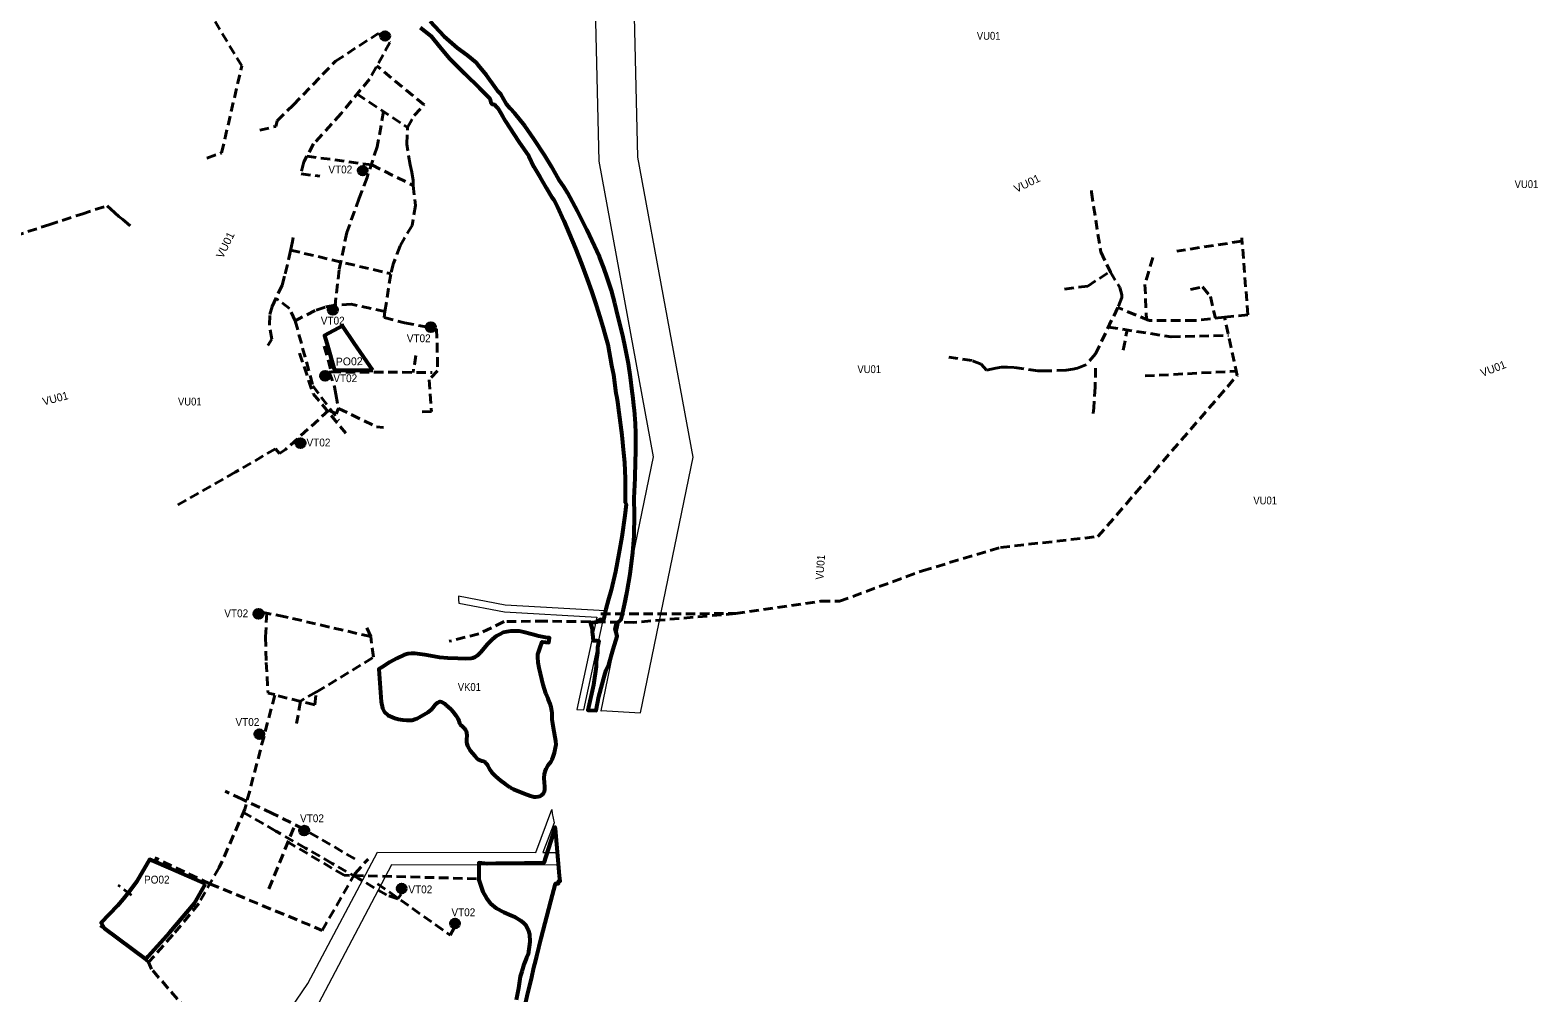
# Model space of a CAD drawing. Extents: x -650145 to -642675, y -1074338 to -1066724.
# Drawn here: x -646512 to -642675, y -1071699 to -1069249 of the extents above; entities that cross this region are included whole.
import ezdxf

# ---------------------------------------------------------------- set-up
doc = ezdxf.new("R2010")
doc.units = 0
doc.header["$LTSCALE"] = 8
doc.linetypes.add('MEDIUM_DASHED', pattern=[4.5, 3, -1.5])
for name, color, linetype in [('1', 7, 'Continuous'), ('17', 7, 'Continuous'), ('2', 7, 'Continuous'), ('5', 7, 'Continuous')]:
    doc.layers.add(name, color=color, linetype=linetype)
for name, color, linetype, lineweight in [('12', 7, 'MEDIUM_DASHED', 40), ('15', 7, 'Continuous', 13), ('45', 7, 'Continuous', 53), ('46', 7, 'Continuous', 53)]:
    doc.layers.add(name, color=color, linetype=linetype, lineweight=lineweight)

msp = doc.modelspace()

# ---------------------------------------------------------------- hatches: boundary and pattern name
at = {"layer": '15'}
for points in [[(-645597.068, -1069264.181, 1), (-645620.593, -1069264.181, 1)], [(-645654.023, -1069606.85, 1), (-645677.548, -1069606.85, 1)], [(-645729.982, -1069961.372, 1), (-645753.507, -1069961.372, 1)], [(-645480.488, -1070005.174, 1), (-645504.013, -1070005.174, 1)], [(-645749.33, -1070128.96, 1), (-645772.855, -1070128.96, 1)], [(-645812.096, -1070300.527, 1), (-645835.621, -1070300.527, 1)], [(-645919.09, -1070734.667, 1), (-645942.615, -1070734.667, 1)], [(-645917.104, -1071041.111, 1), (-645940.629, -1071041.111, 1)], [(-645802.757, -1071286.29, 1), (-645826.282, -1071286.29, 1)], [(-645554.856, -1071433.585, 1), (-645578.381, -1071433.585, 1)], [(-645418.959, -1071522.908, 1), (-645442.484, -1071522.908, 1)]]:
    msp.add_hatch(color=256, dxfattribs=at).paths.add_polyline_path(points)

# ---------------------------------------------------------------- linework, layer by layer
at = {"layer": '12'}
for p, q in [((-645679.959, -1069412.046), (-645551.493, -1069496.874)), ((-645849.328, -1069809.196), (-645594.304, -1069869.281)), ((-643429.636, -1069786.459), (-643594.181, -1069811.599)), ((-643730.467, -1070063.614), (-643720.12, -1070012.253)), ((-645530.465, -1070076.92), (-645537.502, -1070120.198)), ((-643674.528, -1070129.34), (-643442.257, -1070116.937)), ((-645787.95, -1070966.128), (-645887.342, -1070941.864)), ((-645904.71, -1071434.718), (-645838.309, -1071272.923)), ((-645713.277, -1071399.789), (-645855.82, -1071315.589)), ((-646054.42, -1071421.627), (-646194.458, -1071355.655)), ((-646254.398, -1071450.366), (-646287.777, -1071424.84)), ((-645375.745, -1071408.757), (-645713.277, -1071399.789))]:
    msp.add_line(p, q, dxfattribs=at)
for points in [[(-646062.183, -1069574.695), (-646024.736, -1069561.612), (-645973.562, -1069340.254), (-646092.013, -1069143.037), (-646157.557, -1069015.41), (-646220.085, -1068916.892), (-646248.016, -1068862.258), (-646295.932, -1068894.5), (-646451.322, -1069032.874)], [(-645927.806, -1069503.664), (-645886.806, -1069494.297), (-645883.788, -1069480.205), (-645842.55, -1069439.942), (-645734.927, -1069328.215), (-645626.154, -1069257.704), (-645596.435, -1069280.712), (-645648.533, -1069373.739), (-645720.378, -1069461.316), (-645790.62, -1069538.59), (-645815.779, -1069584.682), (-645822.696, -1069614.711), (-645775.097, -1069621.255)], [(-645807.67, -1069569.827), (-645642.853, -1069592.369), (-645537.006, -1069644.608), (-645537.068, -1069631.54), (-645540.509, -1069610.611), (-645545.036, -1069592.007), (-645553.718, -1069539.481), (-645551.493, -1069496.874), (-645535.107, -1069466.529), (-645509.579, -1069439.682), (-645629.872, -1069340.417)], [(-645612.686, -1069456.467), (-645628.75, -1069545.873), (-645654.668, -1069623.875), (-645674.387, -1069676.46), (-645706.032, -1069763.934), (-645725.616, -1069858.975), (-645736.083, -1069949.319)], [(-645537.006, -1069644.608), (-645531.552, -1069695.67), (-645540.071, -1069746.311), (-645570.504, -1069798.227), (-645587.257, -1069841.96), (-645594.542, -1069870.205), (-645609.199, -1069964.997), (-645695.3, -1069946.789), (-645735.674, -1069949.294), (-645761.611, -1069954.176), (-645786.679, -1069962.538), (-645837.185, -1069988.794), (-645851.6, -1069958.035), (-645886.355, -1069931.852)], [(-643810.627, -1069657.665), (-643811.385, -1069662.021), (-643787.529, -1069813.369), (-643763.019, -1069865.538), (-643739.057, -1069904.105), (-643733.398, -1069922.453), (-643733.672, -1069929.3), (-643744.205, -1069955.268), (-643800.43, -1070073.069), (-643825.501, -1070101.354), (-643846.88, -1070109.266), (-643858.108, -1070112.46), (-643875.543, -1070114.925), (-643927.411, -1070116.568), (-643947.688, -1070115.858), (-644007.981, -1070107.962), (-644024.686, -1070106.729), (-644040.027, -1070107.201), (-644054.663, -1070109.432), (-644077.983, -1070114.354), (-644091.49, -1070099.721), (-644115.344, -1070090.018), (-644174.372, -1070081.528)], [(-646552.12, -1069773.25), (-646464.51, -1069744.51), (-646380.87, -1069717.23), (-646346.59, -1069706.12), (-646316.394, -1069696.504), (-646316.32, -1069696.48), (-646306.32, -1069704.97), (-646296.979, -1069713.37), (-646296.125, -1069714.146), (-646285.929, -1069723.39), (-646275.84, -1069731.47), (-646264.46, -1069741.23), (-646257.888, -1069746.914)], [(-645906.816, -1070051.7), (-645897.34, -1070035.615), (-645902.834, -1069999.35), (-645901.735, -1069972.609), (-645895.874, -1069952.462), (-645870.943, -1069898.484), (-645862.678, -1069869.213), (-645849.656, -1069810.695), (-645844.459, -1069786.925), (-645843.101, -1069776.602)], [(-645059.408, -1070735.063), (-644716.965, -1070734.034), (-644500.038, -1070702.585), (-644452.44, -1070702.66), (-644241.161, -1070625.072), (-644042.664, -1070565.642), (-643794.576, -1070538.041), (-643439.868, -1070127.812), (-643472.434, -1069979.54), (-643413.032, -1069974.132), (-643428.496, -1069777.693)], [(-643655.213, -1069827.906), (-643674.851, -1069896.398), (-643671.269, -1069984.982)], [(-643879.717, -1069908.04), (-643820.566, -1069900.574), (-643763.8, -1069863.876)], [(-643558.728, -1069909.08), (-643528.249, -1069902.841), (-643508.036, -1069927.391), (-643495.611, -1069982.269)], [(-645609.199, -1069964.997), (-645611.007, -1069980.138), (-645559.306, -1069994.087), (-645478.278, -1070009.272), (-645476.409, -1070045.777), (-645475.095, -1070115.938), (-645496.905, -1070139.324), (-645490.337, -1070219.995), (-645518.762, -1070220.564)], [(-643472.434, -1069979.54), (-643548.771, -1069988.527), (-643664.391, -1069987.784), (-643744.205, -1069955.268)], [(-645837.185, -1069988.794), (-645792.73, -1070154.35), (-645726.373, -1070242.826)], [(-643767.825, -1070004.757), (-643608.243, -1070029.834), (-643462.149, -1070026.369)], [(-645826.322, -1070071.476), (-645791.882, -1070174.421), (-645708.828, -1070274.697)], [(-645763.769, -1070053.49), (-645745.016, -1070119.16), (-645488.654, -1070120.442)], [(-645745.016, -1070119.16), (-645750.773, -1070119.546), (-645737.216, -1070156.772), (-645734.164, -1070175.48), (-645727.06, -1070211.99), (-645630.95, -1070258.73), (-645613.049, -1070260.16)], [(-643800.52, -1070109.14), (-643801.571, -1070157.278), (-643805.1, -1070210.207), (-643806.511, -1070225.027)], [(-645727.06, -1070211.99), (-645733.17, -1070225.623), (-645751.944, -1070216.719), (-645862.549, -1070316.813), (-645877.139, -1070326.682), (-645887.867, -1070314.667), (-645989.89, -1070374.31), (-646136.792, -1070457.926)], [(-645645.314, -1070792.546), (-645863.469, -1070742.026), (-645925.077, -1070730.137)], [(-645909.628, -1070733.118), (-645913.153, -1070793.741), (-645911.597, -1070858.189), (-645906.549, -1070936.386), (-645889.059, -1070939.608)], [(-644716.965, -1070734.034), (-644976.129, -1070756.486), (-645086.887, -1070754.876), (-645202.78, -1070753.267), (-645305.795, -1070754.34), (-645369.783, -1070785.657), (-645445.374, -1070804.496)], [(-645638.383, -1070845.262), (-645645.314, -1070792.546), (-645658.84, -1070762.42)], [(-645787.95, -1070966.128), (-645783.846, -1070933.893), (-645638.383, -1070845.262)], [(-645783.721, -1070932.909), (-645824.424, -1070957.108), (-645833.925, -1071014.113)], [(-645889.511, -1070941.335), (-645965.547, -1071232.088), (-646030.617, -1071380.071), (-646083.181, -1071471.838), (-646148.926, -1071551.731), (-646210.712, -1071621.148), (-646257.454, -1071581.884), (-646334.001, -1071528.434)], [(-645685.92, -1071358.056), (-645816.424, -1071281.963), (-645895.068, -1071242.641), (-645972.753, -1071206.196), (-646015.628, -1071186.357)], [(-645568.545, -1071446.977), (-645568.85, -1071448.81), (-645576.682, -1071460.349), (-645605.23, -1071449.68), (-645676.24, -1071408.26), (-645743.83, -1071369.64), (-645811.23, -1071330.74), (-645886.93, -1071287.36), (-645969.116, -1071240.205)], [(-646054.42, -1071421.627), (-645768.62, -1071540.17), (-645685.873, -1071396.078), (-645651.868, -1071358.68)], [(-645627.85, -1071421.652), (-645443.026, -1071552.428), (-645433.722, -1071535.133)], [(-645979.173, -1071891.235), (-646007.318, -1071860.17), (-646113.522, -1071742.176), (-646203.196, -1071638.82), (-646210.712, -1071621.148)]]:
    msp.add_lwpolyline(points, dxfattribs=at)
at = {"layer": '15'}
for points in [[(-645047.446, -1068085.007), (-645096.974, -1068231.922), (-645065.08, -1069583.124), (-644926.299, -1070334.854)], [(-644958.761, -1070986.696), (-644824.411, -1070335.926), (-644965.296, -1069572.802), (-644994.849, -1068320.753), (-645000.93, -1068306.11), (-645010.65, -1068282), (-645036.69, -1068221.92), (-645012.64, -1068208.23), (-644990.43, -1068198.75), (-644999.74, -1068171.88), (-645004.64, -1068161.3), (-645014.09, -1068140.85), (-645015.38, -1068138.59), (-645041.75, -1068092.48), (-645047.446, -1068085.007)], [(-644926.299, -1070334.854), (-645059.782, -1070981.425), (-645058.66, -1070981.49), (-645058.472, -1070980.896), (-644958.761, -1070986.696)], [(-645421.999, -1070689.793), (-645422.175, -1070698.418), (-645421.274, -1070707.252)], [(-645103.193, -1070978.912), (-645049.006, -1070727.131), (-645303.017, -1070712.927), (-645421.999, -1070689.793)], [(-645421.274, -1070707.252), (-645305.123, -1070729.835), (-645069.81, -1070742.995)], [(-645069.81, -1070742.995), (-645120.369, -1070977.92), (-645103.193, -1070978.912)], [(-645985.984, -1071889.912), (-645875.751, -1071778.476), (-645805.025, -1071675.361), (-645627.872, -1071341.184), (-645225.385, -1071341.796), (-645184.278, -1071232.417)], [(-645184.278, -1071232.417), (-645183.56, -1071242.5), (-645178.87, -1071266.352), (-645207.234, -1071341.824), (-645170.274, -1071341.88), (-645167.04, -1071373.884), (-645592.784, -1071373.238), (-645786.781, -1071742.105), (-645804.579, -1071731.285)]]:
    msp.add_lwpolyline(points, dxfattribs=at)
at = {"layer": '15', "lineweight": 35}
for centre in [(-645608.83, -1069264.181), (-645665.785, -1069606.85), (-645741.744, -1069961.372), (-645492.25, -1070005.174), (-645761.092, -1070128.96), (-645823.858, -1070300.527), (-645930.852, -1070734.667), (-645928.866, -1071041.111), (-645814.519, -1071286.29), (-645566.618, -1071433.585), (-645430.721, -1071522.908)]:
    msp.add_circle(centre, 11.762, dxfattribs=at)
at = {"layer": '45'}
for points in [[(-645519.59, -1069242.38), (-645491.63, -1069264.25), (-645470.44, -1069291.24), (-645444.62, -1069321.35), (-645405.7, -1069360.27), (-645368.13, -1069397.37), (-645358.04, -1069406.84), (-645342.49, -1069423.06), (-645339.31, -1069433.27), (-645336.66, -1069437.47), (-645330.57, -1069438.89), (-645327.2, -1069442.53), (-645323.36, -1069445.79), (-645322.13, -1069447.96), (-645309.62, -1069467.79), (-645303.57, -1069480.49), (-645268.57, -1069533.23), (-645242.75, -1069570.26), (-645230.42, -1069597.39), (-645230.42, -1069597.39)], [(-645253.4, -1069493.06), (-645278.31, -1069461.33), (-645290.5, -1069449.03), (-645299.61, -1069437.97), (-645306.16, -1069425.55), (-645314.14, -1069412.54), (-645321.1, -1069405.21), (-645326.59, -1069396.64), (-645350.63, -1069363.98), (-645371.12, -1069339.47), (-645376.38, -1069332.65), (-645400.07, -1069313.32), (-645424.8, -1069295.24), (-645458.45, -1069265.56), (-645494.13, -1069227.63)], [(-645230.42, -1069597.39), (-645214.76, -1069622.37), (-645198.41, -1069650.49), (-645185.17, -1069673.38), (-645179.12, -1069681.3), (-645170.3, -1069698.91), (-645153.44, -1069734.71), (-645140.27, -1069766.68), (-645123.84, -1069805.38), (-645108.74, -1069843.58), (-645094.42, -1069882.65), (-645083.31, -1069913.37), (-645071.53, -1069948.89), (-645062.57, -1069978.46), (-645054.73, -1070004.56), (-645047.28, -1070031.83), (-645042.27, -1070049.23), (-645032.21, -1070102.73), (-645027.49, -1070126.56), (-645021.14, -1070173.07), (-645018.56, -1070184.92), (-645016.92, -1070196.32), (-645013.51, -1070222.04), (-645005.98, -1070280.14), (-645001.81, -1070324.58), (-644999.47, -1070349.63), (-644997.87, -1070391.16), (-644998.17, -1070450.59), (-644995.14, -1070455.72), (-644998.92, -1070484.58), (-645006.44, -1070538.78), (-645014.07, -1070580.72), (-645022.64, -1070626.93), (-645033.53, -1070674.55), (-645041, -1070700.44), (-645046.63, -1070722.77), (-645053.21, -1070749.75), (-645060.46, -1070749.1), (-645065.17, -1070751.39), (-645070.3, -1070755.92), (-645085.58, -1070758.04), (-645081.75, -1070772.79), (-645081.85, -1070781.59), (-645081.13, -1070786.56), (-645078.85, -1070802.46), (-645070.2, -1070802.33), (-645065.01, -1070803.22), (-645068.07, -1070820.37), (-645068.52, -1070830.52), (-645068.07, -1070832.72), (-645071.18, -1070855.63), (-645071.77, -1070868.73), (-645078.23, -1070915.65), (-645092.67, -1070979.52), (-645071.99, -1070980.72), (-645064.39, -1070944.7), (-645050.47, -1070891.48), (-645045.74, -1070877.19), (-645043, -1070871.35), (-645039.25, -1070863.33), (-645028.25, -1070824.83), (-645018.18, -1070791.34), (-645023.25, -1070772.62), (-645019.57, -1070760.07), (-645007.68, -1070749.5), (-645001.71, -1070723.39), (-644997.14, -1070700.88), (-644992.6, -1070677.92), (-644985.04, -1070633.43), (-644978.44, -1070578.56), (-644975.05, -1070536.16), (-644974.44, -1070482.48), (-644975.29, -1070440.14), (-644972.48, -1070389.15), (-644971.37, -1070345.98), (-644970.61, -1070323.44), (-644970.36, -1070275.49), (-644971.47, -1070250.14), (-644974, -1070216.2), (-644974.49, -1070210.98), (-644978.49, -1070180.05), (-644979.57, -1070167.9), (-644984.21, -1070132.81), (-644989.62, -1070097.79), (-644996.88, -1070059.73), (-645004.02, -1070026.44), (-645016.01, -1069976.23), (-645024.45, -1069944.43), (-645032.85, -1069912.07), (-645043.5, -1069878.37), (-645051.78, -1069854.2), (-645063.26, -1069825.99), (-645095.1, -1069757.62), (-645118.98, -1069710.08), (-645143.56, -1069664.05), (-645153.33, -1069649.24), (-645166.67, -1069629), (-645184.88, -1069596.58), (-645202.56, -1069568.23), (-645230.1, -1069525.98), (-645253.4, -1069493.06)], [(-645192.548, -1070953.47), (-645193.51, -1070951.2), (-645199.714, -1070937.126), (-645206.872, -1070914.991), (-645216.991, -1070872.38), (-645219.351, -1070858.481), (-645220.312, -1070845.02), (-645219.787, -1070837.502), (-645217.778, -1070830.159), (-645215.063, -1070822.589), (-645208.696, -1070805.535), (-645192.298, -1070807.665), (-645190.59, -1070796.152), (-645200.111, -1070794.621), (-645217.086, -1070791.58), (-645233.003, -1070787.399), (-645255.407, -1070781.443), (-645267.315, -1070779.162), (-645279.349, -1070778.402), (-645288.343, -1070778.909), (-645298.731, -1070780.176), (-645307.923, -1070782.557), (-645317.677, -1070786.866), (-645325.785, -1070791.428), (-645336.046, -1070799.793), (-645348.318, -1070811.675), (-645366.02, -1070832.94), (-645373.241, -1070840.417), (-645379.448, -1070845.106), (-645385.148, -1070847.387), (-645389.329, -1070848.148), (-645404.15, -1070848.781), (-645423.364, -1070848.402), (-645448.7, -1070847.895), (-645470.235, -1070845.487), (-645483.61, -1070843.208), (-645507.299, -1070838.899), (-645533.268, -1070835.731), (-645542.642, -1070835.35), (-645550.832, -1070836.602), (-645560.079, -1070839.137), (-645579.841, -1070848.008), (-645596.689, -1070857.387), (-645615.817, -1070870.187), (-645624.321, -1070875.224), (-645618.798, -1070958.861), (-645615, -1070975), (-645610, -1070985), (-645601.41, -1070992.83), (-645583.707, -1071000.16), (-645575.406, -1071002.782), (-645563.698, -1071004.618), (-645554.524, -1071005.405), (-645548.534, -1071005.316), (-645539.622, -1071004.966), (-645533.156, -1071003.131), (-645527.302, -1071001.033), (-645521.535, -1070997.886), (-645499.204, -1070984.54), (-645494.223, -1070980.781), (-645490.641, -1070977.722), (-645486.534, -1070972.652), (-645481.466, -1070966.271), (-645477.971, -1070963.036), (-645474.301, -1070960.414), (-645471.418, -1070958.578), (-645468.185, -1070957.966), (-645464.865, -1070958.491), (-645462.069, -1070959.89), (-645457.875, -1070962.949), (-645452.982, -1070967.057), (-645448.001, -1070971.341), (-645441.361, -1070977.635), (-645435.443, -1070984.082), (-645428.541, -1070993.348), (-645423.648, -1071000.865), (-645421.21, -1071006.61), (-645419.026, -1071013.254), (-645417.453, -1071016.051), (-645412.735, -1071020.771), (-645407.492, -1071025.841), (-645404.172, -1071029.687), (-645402.194, -1071033.492), (-645401.408, -1071037.251), (-645400.796, -1071044.157), (-645401.233, -1071054.647), (-645401.408, -1071061.465), (-645400.796, -1071065.748), (-645398.979, -1071070.938), (-645395.234, -1071076.602), (-645395.222, -1071076.62), (-645391.902, -1071082.302), (-645380.193, -1071095.851), (-645373.291, -1071103.543), (-645370.698, -1071105.6), (-645367.028, -1071107.348), (-645362.223, -1071108.484), (-645358.326, -1071109.586), (-645358.203, -1071109.621), (-645354.883, -1071111.631)], [(-645354.883, -1071111.631), (-645353.555, -1071112.92), (-645352, -1071114.429), (-645349.99, -1071117.401), (-645347.631, -1071121.771), (-645345.097, -1071126.754), (-645341.689, -1071132.873), (-645336.884, -1071138.467), (-645328.059, -1071147.471), (-645316.308, -1071157.576), (-645303.551, -1071167.541), (-645291.581, -1071175.845), (-645290.83, -1071176.217), (-645281.707, -1071180.74), (-645254.845, -1071191.919), (-645238.506, -1071198.212), (-645230.555, -1071200.135), (-645225.487, -1071200.398), (-645219.283, -1071199.786), (-645215.351, -1071198.562), (-645211.07, -1071196.464), (-645207.575, -1071193.492), (-645205.049, -1071190.531), (-645202.777, -1071186.423), (-645201.903, -1071181.615), (-645202.34, -1071173.66), (-645203.301, -1071164.132), (-645203.738, -1071152.537), (-645202.951, -1071141.698), (-645201.648, -1071136.226), (-645198.678, -1071128.971), (-645193.872, -1071120.142), (-645186.284, -1071110.216), (-645183.401, -1071105.408), (-645180.692, -1071098.24), (-645177.809, -1071088.625), (-645174.225, -1071071.8), (-645173.788, -1071067.691), (-645174.225, -1071057.989), (-645180.164, -1071024.56), (-645182.261, -1071013.633), (-645183.746, -1071003.786), (-645183.833, -1070986.74), (-645184.357, -1070981.146), (-645185.843, -1070972.23), (-645188.377, -1070963.313), (-645192.548, -1070953.47)], [(-645285.617, -1071875.733), (-645244.798, -1071696.585), (-645235.793, -1071663.703), (-645230.436, -1071634.261), (-645227.905, -1071625.277), (-645222.48, -1071606.08), (-645211.27, -1071560.01), (-645186.67, -1071465.55), (-645175.06, -1071420.93), (-645167.58, -1071421.19), (-645167.37, -1071415.2), (-645163.56, -1071415.3), (-645164.76, -1071401.79), (-645175.4, -1071281.93), (-645175.67, -1071279.45), (-645176.14, -1071277.26), (-645204.341, -1071368.19), (-645243.3, -1071369.02), (-645254.27, -1071369.05), (-645327.08, -1071370.05), (-645348.55, -1071370.559), (-645370.24, -1071368.628), (-645370.24, -1071371.074), (-645370.393, -1071396.574), (-645370.24, -1071411.83), (-645359.64, -1071442), (-645351.06, -1071458.3), (-645340.16, -1071471.63), (-645326.29, -1071483.41), (-645306.77, -1071494.16), (-645286.62, -1071502.67), (-645278.52, -1071506.12), (-645262.36, -1071515.72), (-645255.51, -1071521.55), (-645249.88, -1071528.19), (-645244.4, -1071538.48), (-645240.82, -1071549.6), (-645240.26, -1071569.52), (-645244.81, -1071600.61), (-645248.786, -1071610.383), (-645255.662, -1071626.67), (-645261.094, -1071645.025), (-645264.841, -1071657.687), (-645269.077, -1071687.396), (-645274.868, -1071717.176)]]:
    msp.add_lwpolyline(points, dxfattribs=at)
at = {"layer": '46'}
for points in [[(-645639.638, -1070114.895), (-645687.31, -1070045.724), (-645717.36, -1070002.12), (-645762.868, -1070026.606), (-645757.215, -1070045.97), (-645737.075, -1070114.955)], [(-646066.165, -1071422.155), (-646153.5, -1071383.85), (-646208.577, -1071360.044), (-646241.68, -1071416.887), (-646258.487, -1071439.265), (-646275.615, -1071460.886), (-646289.976, -1071477.514), (-646330.914, -1071521.11), (-646324, -1071535), (-646217.978, -1071613.552), (-646211.407, -1071606.247), (-646156.471, -1071545.166), (-646094.063, -1071471.007)]]:
    msp.add_lwpolyline(points, close=True, dxfattribs=at)

# ---------------------------------------------------------------- texts
at = {"layer": '1', "width": 0.9}
msp.add_text('VK01', height=20, dxfattribs=at).set_placement((-645423.759, -1070930.954))
at = {"layer": '17', "width": 0.95}
for p in [(-645753.107, -1069613.825), (-645772.41, -1069998.573), (-645553.491, -1070043.441), (-645740.516, -1070145.097), (-645808.603, -1070308.709), (-646017.95, -1070743.342), (-645989.445, -1071019.949), (-645825.148, -1071264.946), (-645549.442, -1071445.886), (-645439.959, -1071504.162)]:
    msp.add_text('VT02', height=20, dxfattribs=at).set_placement(p)
at = {"layer": '2', "width": 0.9}
for p in [(-644102.761, -1069273.709), (-642734.104, -1069651.125), (-644406.791, -1070121.981), (-646135.912, -1070204.401), (-643399.108, -1070456.171)]:
    msp.add_text('VU01', height=20, dxfattribs=at).set_placement(p)
at = {"layer": '2'}
for rotation, width, p in [(25.964, 1.05, (-644002.392, -1069663.63)), (63.768, 1.05, (-646021.976, -1069831.992)), (85.874, 0.95, (-644493.521, -1070648.37))]:
    msp.add_text('VU01', height=20, rotation=rotation, dxfattribs=dict(at, width=width)).set_placement(p)
for rotation, p in [(20.965, (-642816.364, -1070131.907)), (14.511, (-646477.81, -1070204.543))]:
    msp.add_text('VU01', height=20, rotation=rotation, dxfattribs=at).set_placement(p)
at = {"layer": '5'}
msp.add_text('PO02', height=20, rotation=1.088, dxfattribs=at).set_placement((-645734, -1070102.958))
at = {"layer": '5', "width": 0.95}
msp.add_text('PO02', height=20, dxfattribs=at).set_placement((-646222.248, -1071421.051))

doc.saveas('drawing.dxf')
